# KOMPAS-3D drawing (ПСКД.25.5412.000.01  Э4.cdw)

Referenced files in C:\Users\artyhina\Desktop\ШСУ_24-07-02 _2ЯрКлеммы_1КанБП_БАРС-Лайт -\: СПО КД.25.0000.000.00-00 Э4.cdw
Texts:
  ПСКД.25.54ХХ.000.01 Э4
  Шкаф связи и управления ШСУ-54-ХХ-01 Схема электрическая соединений
  Локальный фрагмент 1
  Приборы, устройства
  Продолжение таблицы 2 (для исп. СПО КД.25.0000.000.00-02 - ШСУ-24-07-02)
  устройства
  Контакты
  Клемма,
  разъём
  наконечника
  (AM  (ШСУ-24-0Х-02))
  XP1
  болт
  заземления
  КК2
  AM  (ШСУ-24-0Х-02)
  G2 (10ВР220-12Д)
  G3 (10ВР220-12Д)
  G4 (10ВР220-12Д)
  G5 (10ВР220-12Д)
  G6 (10ВР220-12Д)
  G7 (10ВР220-12Д)
  XP2
  болт заземления
  клемма заземления
  ХТ6-2
  AM (AM  (ШСУ-24-0Х-02))
  Фигурная скобка
  Normal
  спрятанное
  layer 1
  Позиционное
  обозначение
  AM (ШСУ-24-XX)
  A1 (ВКТ-7-04)
  выход
  КК6, КК6,
  КК6
  XT2-1
  INV+
  INV-
  HL (лампа)
  (выключатель
  автоматический)
  (ШСУ-24-XX)
  G7 (DR-15-12)
  ХТ6-1
  (10ВР220-12Д)
  XT6-2
  XS (Розетка)
  AM (ШСУ - крышка)
  G7 (MDR-20-12)
  Таблица 3 - Описание наконечников
  Типоразмер (сечение)
  Цвет
  Тип
  Красный
  Гильзовый двойной
  Белый
  Гильзовый
  Кольцевой
  КК8
  Желтый
  Оранжевый
  Поз. обоз-
  начение
  Таблица 3 - Перечень элементов, расположенных в шкафу
  Кол.
  XР1, XР2
  XT1
  XT2
  XT3
  XT4
  XT5
  XT6
  Вычислитель количества теплоты ТВ-7.04
  Шкаф связи и управления ШСУ-54-ХХ
  Блок автоматический регистрационно-связной БАРС-02-Р-3-П
  Блок питания одноканальный модульного исполнения DR-15-12
  Блок питания двуканальный модульного исполнения БП 2/12-03
  Блок питания одноканальный модульного исполнения 10ВР220-12Д
  Лампа коммутационная красная светодиодная U 220В, I 20 мА
  Выключатель автоматический 2P; U e 230/400 В; хар-ка С; I ном 16А
  Болт заземления шкафа (фальшпанель, крышка)
  Klemsan YBK 2,5 (серый) на DIN-рейку ИЭК
  Розетка модульная с контактом заземлением 16А
  для питания БАРС
  для питания ИПД
  для питания ИПД и ИПР
  для извещателя
  для питания ИПР
  для сигнала ИПР
  для питания QF
  для ИПД
  Таблица 2 - Описание наконечников
  Изделие
  Таблица 1 - Исполнение
  Рис.
  Схема
  Табл.
  ШСУ-54-12-01
  ПСКД.25.5412.000.01
  ПСКД.25.5412.000.01 Э4
  ШСУ-54-22-01
  ШСУ-54-32-01
  ШСУ-54-33-01
  ПСКД.25.5422.000.01
  ПСКД.25.5422.000.01 Э4
  ПСКД.25.5432.000.01
  ПСКД.25.5433.000.01
  ПСКД.25.5432.000.01 Э4
  ПСКД.25.5433.000.01 Э4
  ЛК1
  АМ (Шкаф связи и управления
  ШСУ-54-22-01)
  Рис. 2 Схема электрическая внутренних соединений шкафа связи и управления ШСУ-54-22-01 (ПСКД.25.5422.000.01)
  ХТ4
  ХР1
  БП 2/12-03
  UP 1
  UP 2
  Дверца
  шкафа
  (БАРС-02-Р-3-П)
  Вычислитель
  "ТВ7-04"
  PWR
  SMA(f)
  Общ
  AM  (ШСУ-54-22-01)
  Откуда
  Таблица 5 (для исп. ПСКД.25.5422.000.01 - ШСУ-54-22-01)
  Куда
  ХТ6
  ХТ4-1
  G2 (БП2/12-03)
  G3 (БП2/12-03)
  G1 (DR-15-12)
  UP1
  UP2
  A2 (Барс-03-Р-3-П)
  SMA(F)
  GND
  (DR-15-12)
  Антена GSM
  PwR
  А1 (ТВ-7-04)
  (БАРС)
  ХТ8
  RTS
  (БАРС RS-232)
  XT13
  XT3-1
  XT3-2
  XT5-1, XT5-2
  XT5-3, XT5-4
  ХТ1
  (вход)
  XT15
  XT3-3
  XT3-4
  XT3-5
  XT3-6
  XТ5
  SHLD
  Конт.
  Цепь
  XТ14
  XТ15
  XТ13
  XТ8
  XТ2
  DB-9S
  RS-232
  DB-9M
  RxD
  TxD
  ХТ2
  AM (ШСУ-54-22-01)
  RTS, RTS
  (ТВ-7-04)
  A1 (ТВ-7-04)
  АM (ШСУ-54-22-01)
  К термопреобразователю
  ИТП1-3
  Лист
  Изм.
  № докум.
  Подп.
  Дата
  Инв. № подл.
  Подп. и дата
  Взам. инв. №
  Инв. № дубл.
  Питание
  ИПР1 -3
  Сигнал
  ИПД1-3
  ИПТ1 -3
  Изв.1  Изв.2
  Схему соединений выбрать по таблице 1; наконечники для проводов приведены   в
  таблице 2;   перечень   подключаемых    элементов - в таблице 3, порядок
  соединения в  таблице 4,5,6,7
  Наконечники обжать клещами обжимными, соответствующего типа.  Разрывы
  гильзы  или  изолирующей   втулки   наконечника   не допускаются.
  Наконечники использовать для проводов: питающих - жёлтого цвета; сигнальных
  - белого и оранжевого цвета; заземляющих - кольцевые красного цвета (под болты
  заземления XP1 корпуса и панели, XP2 дверцы шкафа), жёлтого цвета (для розетки
  XS); для перемычек - красного цвета под два провода.
  Подключение автоматического выключателя и соединение устройств выполнить
  кабелем ПВ3 0,5; заземление - ПВ3 1,0.
  Подключение блока БАРС, блоков питания БП-2/12-03 к питанию допускается
  выполнять путём доработки шнура сетевого данных устройств.
  Шкаф связи и управления
  ШСУ-54-ХХ-01
  Схема электрическая соединений
  Артюхина Е.С.
  Науменко Т.В.
  Нач. отдела
  Журавлёв А.А.
  Ещенко С.Н.
  ЗАО "ПромСервис"
  г. Димитровград
  СПО КД.25.0000.000.00-00 Э4-
  Поймалов С.В.
Dimensions and other numbers on the sheet: 6; 5; 8; 10; 0; 2; 4; 1; 3; 7; 2 1,5 мм; 0,75 мм; 1,0 мм; 0,50 мм; 12; -12; -22; -32; -33; 1,5 мм; 2х0,75 мм; 2х1,0 мм; 2х0,50 мм; 1,  3, 5; 2,  4, 6; +12B; 4, 2; 8, 6; 2, 4; 6, 8; 3, 1; 7, 5; 10, 11, 12; 9; 7, 8; 11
